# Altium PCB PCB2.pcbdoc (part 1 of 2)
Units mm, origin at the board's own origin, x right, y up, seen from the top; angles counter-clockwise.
Board outline 189.74 x 136.02 mm, 2 copper layers (Top Layer, Bottom Layer); 111 components, 66 nets, 434 pads, 460 vias.
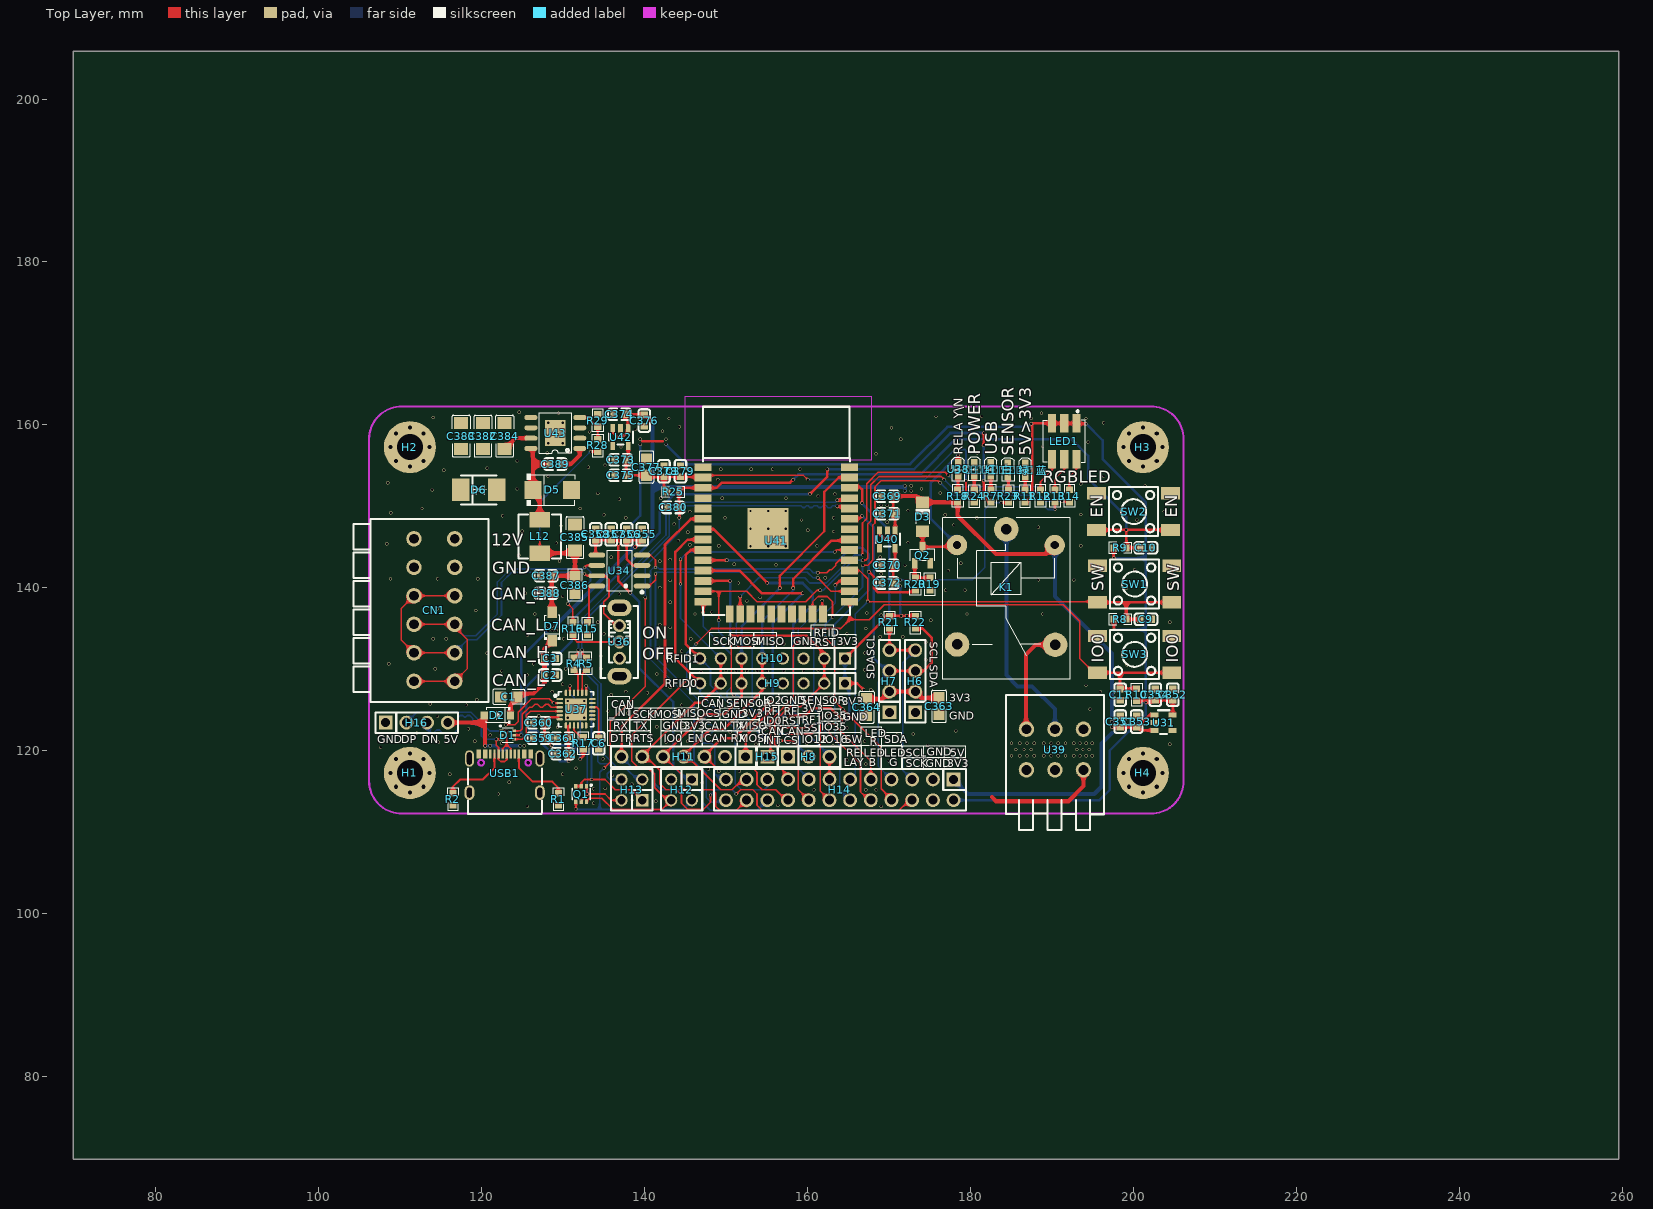
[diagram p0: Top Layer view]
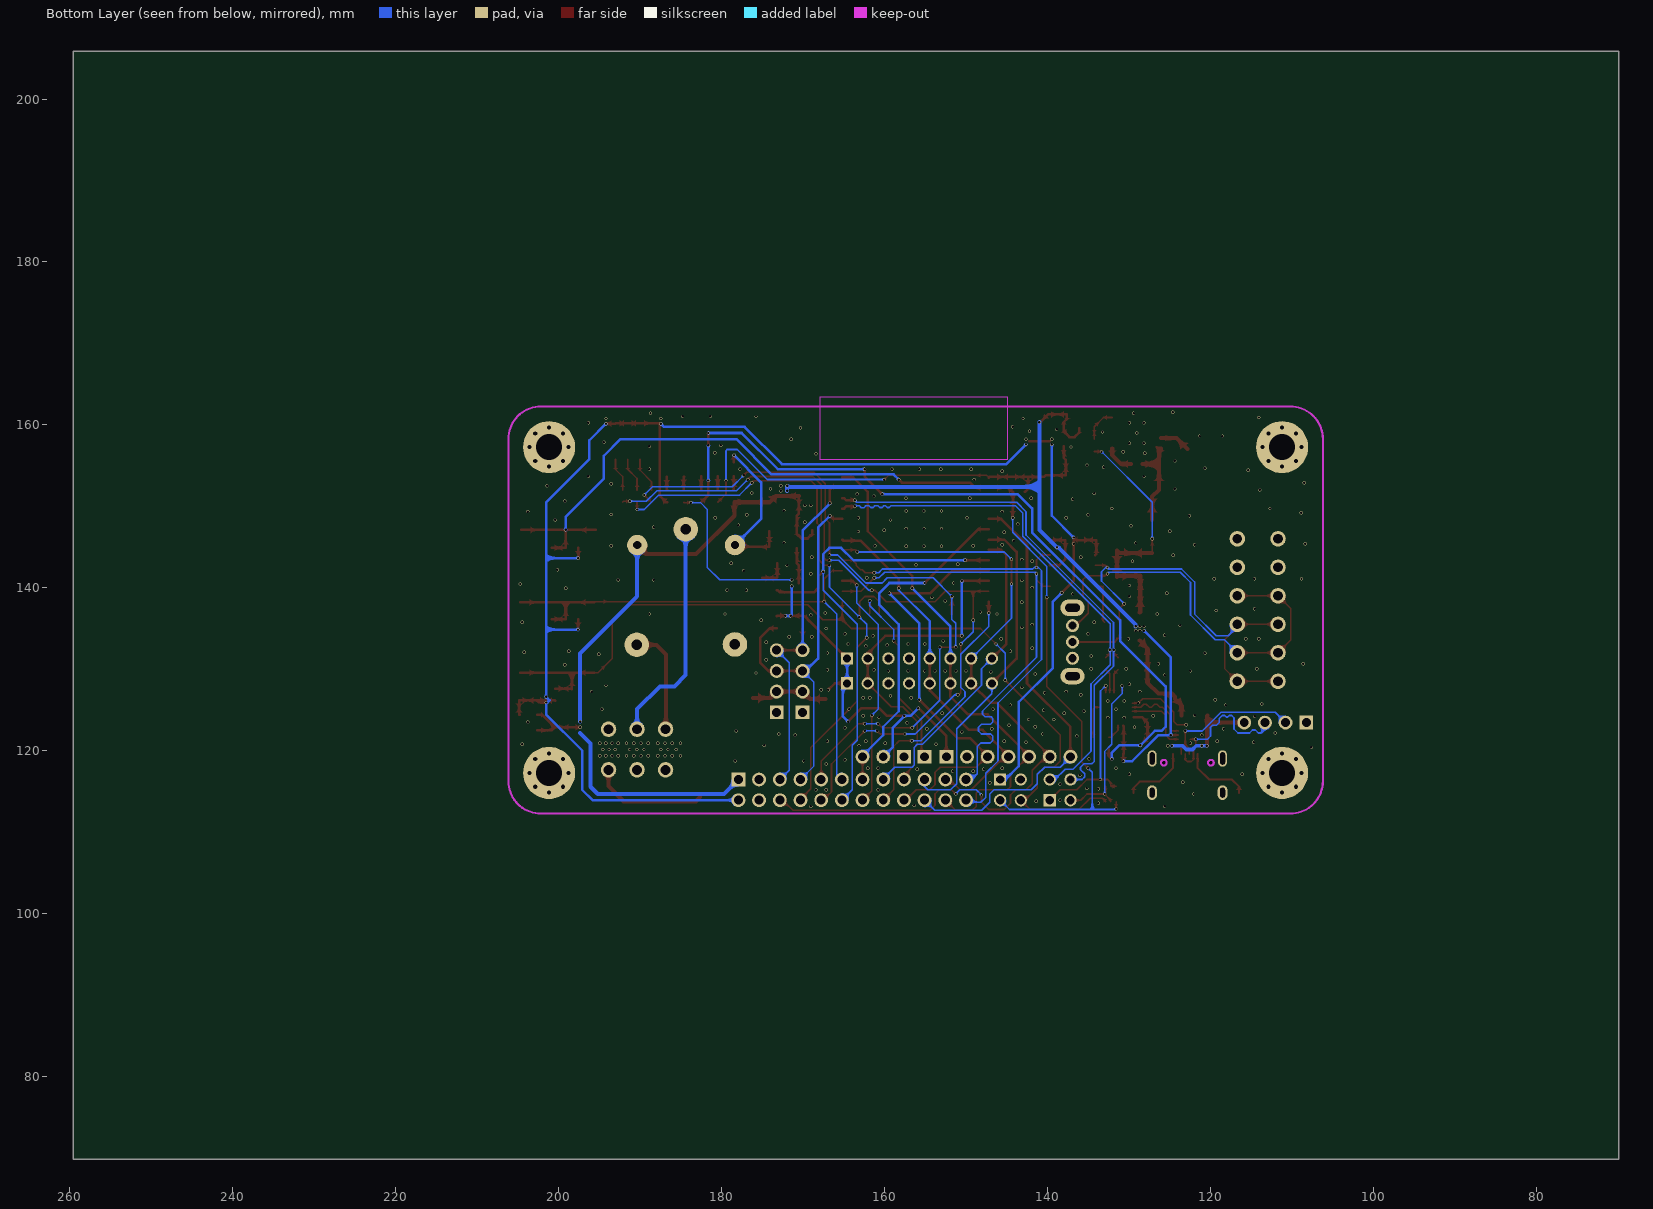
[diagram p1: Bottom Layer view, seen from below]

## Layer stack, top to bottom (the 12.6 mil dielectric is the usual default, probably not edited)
Top Layer: signal copper (thickness not stored)
Dielectric: dielectric 0.32, FR-4, Dk 4.8
Bottom Layer: signal copper (thickness not stored)

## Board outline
259.588,69.85 69.85,69.85 69.85,205.867 259.588,205.867

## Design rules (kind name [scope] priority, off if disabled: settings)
Clearance copperThickness1oz [All] p1: gap=0.178 ignorepadtopadclearanceinfootprint=FALSE except(0.099: Track-Track Track-SMDPad SMDPad-SMDPad Track-THPad SMDPad-THPad THPad-THPad Track-Via SMDPad-Via THPad-Via Via-Via Track-Fill SMDPad-Fill THPad-Fill Via-Fill Fill-Fill Track-Region SMDPad-Region THPad-Region Via-Region Fill-Region Region-Region Track-Poly SMDPad-Poly THPad-Poly Via-Poly Fill-Poly Region-Poly Poly-Poly Track-Text SMDPad-Text THPad-Text Via-Text Fill-Text Region-Text Poly-Text Text-Text Track-Hole SMDPad-Hole THPad-Hole Via-Hole Fill-Hole Region-Hole Poly-Hole Text-Hole; 0.254: SMDPad-Sheet; 0.3: Track-Sheet THPad-Sheet Via-Sheet Fill-Sheet Region-Sheet Poly-Sheet Text-Sheet Sheet-Hole)
Clearance copperThickness2oz [All] p1: gap=0.178 ignorepadtopadclearanceinfootprint=FALSE except(0.152: Track-SMDPad SMDPad-SMDPad Track-THPad SMDPad-THPad THPad-THPad Track-Via SMDPad-Via THPad-Via Via-Via Track-Fill SMDPad-Fill THPad-Fill Via-Fill Fill-Fill SMDPad-Region THPad-Region Via-Region Fill-Region Region-Region Track-Poly SMDPad-Poly THPad-Poly Via-Poly Fill-Poly Poly-Poly Track-Text SMDPad-Text THPad-Text Via-Text Fill-Text Region-Text Poly-Text Text-Text Track-Hole SMDPad-Hole THPad-Hole Via-Hole Fill-Hole Region-Hole Poly-Hole Text-Hole; 0.203: Track-Track; 0.3: Track-Region Region-Poly Track-Sheet SMDPad-Sheet THPad-Sheet Via-Sheet Fill-Sheet Region-Sheet Poly-Sheet Text-Sheet Sheet-Hole)
Clearance copperThicknessInner0.5oz [All] p1: gap=0.178 ignorepadtopadclearanceinfootprint=FALSE except(0.089: Track-Track; 0.152: Track-SMDPad SMDPad-SMDPad Track-THPad SMDPad-THPad THPad-THPad Track-Via SMDPad-Via THPad-Via Via-Via Track-Fill SMDPad-Fill THPad-Fill Via-Fill Fill-Fill SMDPad-Region THPad-Region Via-Region Fill-Region Region-Region Track-Poly SMDPad-Poly THPad-Poly Via-Poly Fill-Poly Poly-Poly Track-Text SMDPad-Text THPad-Text Via-Text Fill-Text Region-Text Poly-Text Text-Text Track-Hole SMDPad-Hole THPad-Hole Via-Hole Fill-Hole Region-Hole Poly-Hole Text-Hole; 0.3: Track-Region Region-Poly Track-Sheet SMDPad-Sheet THPad-Sheet Via-Sheet Fill-Sheet Region-Sheet Poly-Sheet Text-Sheet Sheet-Hole)
DiffPairsRouting differentialPair [All] p1: maxuncoupledlength=10 maxlimit=7.874 mostfreqgap=7.874 toplayer_minwidth=5 toplayer_prefwidth=10 toplayer_maxwidth=100 bottomlayer_minwidth=5 bottomlayer_prefwidth=10 bottomlayer_maxwidth=100
PasteMaskExpansion pasteMaskExpansion [All] p1:
PlaneConnect innerPlane [All] p1: planeconnectstyle=Relief reliefexpansion=0.508 reliefentries=4 reliefconductorwidth=0.254 reliefairgap=0.254
PolygonConnect copperRegionvusb [All] p1: connectstyle=Direct reliefentries=4 reliefconductorwidth=10 polygonreliefangle="90 Angle" airgapwidth=10
PolygonConnect copperRegion0p2 [All] p1: connectstyle=Direct reliefentries=4 reliefconductorwidth=10 polygonreliefangle="90 Angle" airgapwidth=10
PolygonConnect copperRegion1 [All] p1: connectstyle=Direct reliefentries=4 reliefconductorwidth=10 polygonreliefangle="90 Angle" airgapwidth=10
RoutingVias viaSize [All] p1: viastyle="Through Hole" holewidth=11.811 minholewidth=11.811 maxholewidth=248.0314 width=15.748 minwidth=15.748 maxwidth=393.7008
SolderMaskExpansion solderMaskExpansion [All] p1: useseparateexpansions=TRUE expansion=2.0079 expansionbottom=2.0079
Width copperThickness1oz [All] p1: maxlimit=394 minlimit=4 preferedwidth=8
Width copperThickness0.5oz [All] p1: maxlimit=100 minlimit=4 preferedwidth=10
Width copperThickness2oz [All] p1: maxlimit=100 minlimit=8 preferedwidth=10

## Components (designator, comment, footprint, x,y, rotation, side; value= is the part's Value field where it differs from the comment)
C1 "CGA0805X5R226M350MT" C0805 123.317,126.619 r180 top
C2 "CL10A106MA8NRNC" C0603 128.397,129.286 r0 top
C3 "CGA0603X7R104K500JT" C0603 128.397,131.318 r0 top
C6 "CGA0603X5R475K250JT" C0603 134.366,120.904 r90 top
C9 "CGA0603X7R104K500JT" C0603 201.549,136.144 r0 top
C10 "CGA0603X7R104K500JT" C0603 201.549,144.907 r0 top
C11 "CGA0603X7R104K500JT" C0603 198.374,126.873 r270 top
C351 "CL10A106MA8NRNC" C0603 198.374,123.571 r270 top
C352 "CL10A106MA8NRNC" C0603 204.851,126.873 r270 top
C353 "CGA0603X7R104K500JT" C0603 200.406,123.571 r270 top
C354 "CGA0603X7R104K500JT" C0603 202.692,126.873 r270 top
C355 "CL10A106MA8NRNC" C0603 139.7,146.558 r270 top
C356 "CGA0603X7R104K500JT" C0603 137.795,146.558 r270 top
C357 "CL10A106MA8NRNC" C0603 135.89,146.558 r270 top
C358 "CGA0603X7R104K500JT" C0603 133.985,146.558 r270 top
C359 "CGA0603X7R104K500JT" C0603 127,121.539 r0 top
C360 "CGA0603X5R475K250JT" C0603 127,123.444 r0 top
C361 "CL10A106MA8NRNC" C0603 129.921,121.539 r0 top
C362 "CGA0603X7R104K500JT" C0603 129.921,119.634 r0 top
C363 "CGA0805X5R226M350MT" C0805 176.149,125.476 r270 top
C364 "CGA0805X5R226M350MT" C0805 167.259,125.349 r270 top
C369 "CL10A106MA8NRNC" C0603 169.799,151.257 r0 top
C370 "CL10A106MA8NRNC" C0603 169.799,142.748 r0 top
C371 "CGA0603X7R104K500JT" C0603 169.799,149.098 r0 top
C372 "CGA0603X7R104K500JT" C0603 169.799,140.589 r0 top
C373 "CL10A106MA8NRNC" C0603 137.033,155.702 r0 top
C374 "CGA0603X7R104K500JT" C0603 136.906,161.29 r0 top
C375 "CGA0603X7R104K500JT" C0603 137.033,153.797 r0 top
C376 "CL10A106MA8NRNC" C0603 139.954,160.528 r90 top
C377 "CGA0805X5R226M350MT" C0805 140.208,154.813 r90 top
C378 "CL10A106MA8NRNC" C0603 142.367,154.305 r90 top
C379 "CGA0603X7R104K500JT" C0603 144.399,154.305 r90 top
C380 "CGA0603X7R104K500JT" C0603 143.51,149.86 r180 top
C382 "HGC1206R5106K500NSPJ" C1206 120.142,158.623 r270 top
C383 "CGA1206X5R226M350NT" C1206 117.475,158.623 r270 top
C384 "CL31B104KBCNNNC" C1206 122.809,158.623 r270 top
C385 "HGC1206R5476M250NSPJ" C1206 131.445,146.177 r270 top
C386 "CGA0805X5R226M350MT" C0805 131.445,140.335 r90 top
C387 "CL10A106MA8NRNC" C0603 127.889,141.478 r0 top
C388 "CGA0603X7R104K500JT" C0603 127.889,139.319 r0 top
C389 "CGA0603X7R104K500JT" C0603 129.032,155.194 r0 top
CN1 "New_Library_2601-1106" CONN-TH_2601-1106 114.172,137.268 r270 top
D1 "USBLC6-2P6_C2827693" SOT-666-6_L1.6-W1.2-P0.50-LS1.6-BL 123.19,121.92 r270 top
D2 "5819W" SOD-123_L2.7-W1.6-LS3.7-FD 121.92,124.333 r0 top
D3 "LL4148-GS08" SOD-80_L3.5-W1.5-RD 174.117,148.717 r270 top
D5 "SS54SMB" SMB_L4.6-W3.6-LS5.3-RD 128.651,152.019 r0 top
D6 "SMBJ28A" SMB_L4.6-W3.6-LS5.3-L-FD 119.634,152.019 r180 top
D7 "DSK34_C7502709" SOD-123FL_L2.7-W1.8-LS3.8-RD 128.651,135.255 r90 top
H1 "Mechanical_MountingHole_Pad" MountingHole:MountingHole_3.2mm_M3_Pad_Via 111.172,117.268 r0 top
H2 "Mechanical_MountingHole_Pad" MountingHole:MountingHole_3.2mm_M3_Pad_Via 111.172,157.268 r0 top
H3 "Mechanical_MountingHole_Pad" MountingHole:MountingHole_3.2mm_M3_Pad_Via 201.172,157.268 r0 top
H4 "Mechanical_MountingHole_Pad" MountingHole:MountingHole_3.2mm_M3_Pad_Via 201.172,117.268 r0 top
H6 "PZ254V-11-04P" HDR-TH_4P-P2.54-V-M 173.228,128.524 r90 top
H7 "PZ254V-11-04P" HDR-TH_4P-P2.54-V-M 170.053,128.524 r90 top
H8 "PZ254V-11-03P" HDR-TH_3P-P2.54-V-M 160.147,119.253 r0 top
H9 "PZ254V-11-08P" HDR-TH_8P-P2.54-V-M 155.702,128.27 r180 top
H10 "PZ254V-11-08P" HDR-TH_8P-P2.54-V-M 155.702,131.318 r180 top
H11 "HX PZ2.54-1x7P ZZ" HDR-TH_7P-P2.54-V-M 144.78,119.253 r180 top
H12 "HX PZ2.54-2x2P ZZ" HDR-TH_HX-PZ2.54-2X2P-ZZ 144.526,115.189 r180 top
H13 "HX PZ2.54-2x2P ZZ" HDR-TH_HX-PZ2.54-2X2P-ZZ 138.43,115.189 r90 top
H14 "PZ254V-12-24P" HDR-TH_24P-P2.54-V-M-R2-C12-S2.54 163.957,115.189 r180 top
H15 "PZ254V-11-01P" HDR-TH_1P-P2.54-V-M 155.067,119.253 r0 top
H16 "PZ254V-11-04P" HDR-TH_4P-P2.54-V-M 112.014,123.444 r0 top
K1 "Relay_SANYOU_SRD_Form_C" Relay_THT:Relay_SPDT_SANYOU_SRD_Series_Form_C 184.404,147.193 r270 top
L12 "FXL0530-100-M" IND-SMD_L5.4-W5.2_FXL0530 127.127,146.304 r270 top
LED1 "TC5050RGBF08-3CJH-AF53A" LED-SMD_6P-L5.0-W5.0-TL_TC5050RGBF08 191.516,157.988 r270 top
LED白 "NCD0603W1" LED0603-RD 182.499,154.432 r270 top
LED红 "SZYY0603R" LED0603-R-RD 180.467,154.559 r270 top
LED绿 "XL-1608PGC-06" LED0603-RD_GREEN 184.658,154.432 r270 top
LED蓝 "SZYY0603B" LED0603-R-RD_BLUE 186.69,154.432 r270 top
Q1 "UMH3N" SC-70-6_L2.2-W1.3-P0.65-LS2.1-BR 132.207,114.681 r90 top
Q2 "BC817_C916383" SOT-23-3_L2.9-W1.3-P1.90-LS2.4-BR 174.117,144.018 r270 top
R1 "0603WAF5101T5E" R0603 129.413,114.046 r270 top
R2 "0603WAF5101T5E" R0603 116.459,114.046 r270 top
R4 "0603WAF220JT5E" R0603 131.318,130.683 r90 top
R5 "0603WAF220JT5E" R0603 132.842,130.683 r90 top
R7 "0603WAF1002T5E" R0603 182.499,151.257 r90 top
R8 "0603WAF1002T5E" R0603 198.374,136.144 r180 top
R9 "0603WAF1002T5E" R0603 198.374,144.907 r180 top
R10 "0603WAF1002T5E" R0603 200.406,126.873 r270 top
R11 "0603WAF1002T5E" R0603 186.69,151.257 r270 top
R12 "0603WAF1001T5E" R0603 188.595,151.257 r90 top
R13 "0603WAF1001T5E" R0603 190.373,151.257 r90 top
R14 "0603WAF1001T5E" R0603 192.151,151.257 r90 top
R15 "0603WAF0000T5E" R0603 132.969,135.001 r270 top
R16 "0603WAF220JT5E" R0603 131.191,135.001 r90 top
R17 "0603WAF4701T5E" R0603 132.461,120.904 r90 top
R18 "0603WAF1002T5E" R0603 178.435,151.257 r90 top
R19 "0603WAF1002T5E" R0603 175.006,140.462 r270 top
R20 "0603WAF1001T5E" R0603 173.228,140.462 r90 top
R21 "0603WAF4701T5E" R0603 170.053,135.763 r270 top
R22 "0603WAF4701T5E" R0603 173.228,135.763 r270 top
R23 "0603WAF1002T5E" R0603 184.658,151.257 r270 top
R24 "0603WAF1002T5E" R0603 180.467,151.257 r270 top
R25 "0603WAF1002T5E" R0603 143.51,151.765 r0 top
R28 "0603WAF1002T5E" R0603 134.239,157.48 r270 top
R29 "FRC0603F3161TS" R0603 134.239,160.528 r90 top
SW1 "KH-6X6X5H-STM" SW-SMD_4P-L6.0-W6.0-P4.50-LS9.0_H5.0 200.152,140.462 r0 top
SW2 "KH-6X6X5H-STM" SW-SMD_4P-L6.0-W6.0-P4.50-LS9.0_H5.0 200.025,149.352 r0 top
SW3 "KH-6X6X5H-STM" SW-SMD_4P-L6.0-W6.0-P4.50-LS9.0_H5.0 200.152,131.826 r0 top
U31 "ME6211C30M5G-N" SOT-23-5_L2.9-W1.6-P0.95-LS2.8-BL 203.708,123.444 r270 top
U34 "TJA1051T/3/1J" SOIC-8_L4.9-W3.9-P1.27-LS6.0-BL 136.906,142.113 r90 top
U36 "HX SS12D07VG5" SW-TH_SS12D07VG3 136.906,133.35 r270 top
U37 "CP2104-F03-GMR" QFN-24_L4.0-W4.0-P0.50-BL-EP2.7 131.572,125.095 r270 top
U38 "MHT192WDT-GOLD" LED0603-RD-YELLOW 178.435,154.432 r270 top
U39 "2601-1103" CONN-TH_6P-P3.50_2601-1103 190.373,120.142 r0 top
U40 "ME6211C30M5G-N" SOT-23-5_L2.9-W1.6-P0.95-LS2.8-BL 169.799,145.953 r180 top
U41 "ESP32-WROOM-32D-N4" WIFIM-SMD_39P-L25.5-W18.0-P1.27-BL 156.172,145.796 r270 top
U42 "ME6211C30M5G-N" SOT-23-5_L2.9-W1.6-P0.95-LS2.8-BL 137.033,158.496 r180 top
U43 "TPS5450MDDAREP" POWERPAD-SO-8_L4.9-W3.9-P1.27-LS6.0-BL-EP 129.032,159.004 r90 top
USB1 "TYPE-C 16PIN 2MD(073)" USB-C-SMD_TYPE-C-6PIN-2MD-073 122.809,117.221 r0 top

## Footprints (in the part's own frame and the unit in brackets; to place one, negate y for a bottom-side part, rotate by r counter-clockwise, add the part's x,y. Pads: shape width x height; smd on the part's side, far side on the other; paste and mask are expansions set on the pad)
C0603 [mm]
  rect 0.8x0.9 smd: 1(-0.7,0) 2(0.7,0)
  silkscreen extent -1.39,-0.71 1.39,0.71
C0805 [mm]
  rect 1.41x1.35 smd: 1(-1,0) 2(1,0)
  silkscreen extent -1.96,-0.9 1.96,0.9
C1206 [mm]
  rect 1.485x1.728 smd: 1(-1.593,0) 2(1.593,0)
  silkscreen extent -2.56,-1.09 2.56,1.09
CONN-TH_6P-P3.50_2601-1103 [mm]
  round 1.9 hole 1.2: 1(-3.5,2.5) 2(-3.5,-2.5) 3(0,2.5) 4(0,-2.5) 5(3.5,2.5) 6(3.5,-2.5)
  silkscreen extent -6,-9.9 6,6.7
CONN-TH_2601-1106 [mm]
  round 1.9 hole 1.2: 1(-8.75,-2.5) 1(-8.75,2.5) 2(-5.25,2.5) 2(-5.25,-2.5) 3(-1.75,2.5) 3(-1.75,-2.5) 4(1.75,2.5) 4(1.75,-2.5) 5(5.25,2.5) 5(5.25,-2.5) 6(8.75,-2.5) 6(8.75,2.5)
  silkscreen extent -11.19,-9.93 11.31,6.65
HDR-TH_1P-P2.54-V-M [mm]
  rect 1.7x1.7 hole 1.1: 1(0,0)
  silkscreen extent -1.27,-1.27 1.27,1.27
HDR-TH_3P-P2.54-V-M [mm]
  rect 1.7x1.7 hole 1.1: 1(-2.54,0)
  round 1.7 hole 1.1: 2(0,0) 3(2.54,0)
  silkscreen extent -3.81,-1.25 3.81,1.25
HDR-TH_4P-P2.54-V-M [mm]
  rect 1.7x1.7 hole 1.1: 1(-3.81,0)
  round 1.7 hole 1.1: 2(-1.27,0) 3(1.27,0) 4(3.81,0)
  silkscreen extent -5.08,-1.27 5.08,1.27
HDR-TH_7P-P2.54-V-M [mm]
  rect 1.7x1.7 hole 1.1: 1(-7.62,0)
  round 1.7 hole 1.1: 2(-5.08,0) 3(-2.54,0) 4(0,0) 5(2.54,0) 6(5.08,0) 7(7.62,0)
  silkscreen extent -8.89,-1.25 8.89,1.25
HDR-TH_8P-P2.54-V-M [mm]
  rect 1.5x1.5 hole 1: 1(-8.89,0)
  round 1.5 hole 1: 2(-6.35,0) 3(-3.81,0) 4(-1.27,0) 5(1.27,0) 6(3.81,0) 7(6.35,0) 8(8.89,0)
  silkscreen extent -10.16,-1.27 10.16,1.27
HDR-TH_24P-P2.54-V-M-R2-C12-S2.54 [mm]
  rect 1.7x1.7 hole 1.1: 1(-13.97,-1.27)
  round 1.7 hole 1.1: 2(-13.97,1.27) 3(-11.43,-1.27) 4(-11.43,1.27) 5(-8.89,-1.27) 6(-8.89,1.27) 7(-6.35,-1.27) 8(-6.35,1.27) 9(-3.81,-1.27) 10(-3.81,1.27) 11(-1.27,-1.27) 12(-1.27,1.27) 13(1.27,-1.27) 14(1.27,1.27) 15(3.81,-1.27) 16(3.81,1.27) 17(6.35,-1.27) 18(6.35,1.27) 19(8.89,-1.27) 20(8.89,1.27) 21(11.43,-1.27) 22(11.43,1.27) 23(13.97,-1.27) 24(13.97,1.27)
  silkscreen extent -15.47,-2.54 15.47,2.54
HDR-TH_HX-PZ2.54-2X2P-ZZ [mm]
  rect 1.5x1.5 hole 1.02: 1(-1.27,-1.27)
  round 1.5 hole 1.02: 2(-1.27,1.27) 3(1.27,-1.27) 4(1.27,1.27)
  silkscreen extent -2.54,-2.54 2.54,2.54
IND-SMD_L5.4-W5.2_FXL0530 [mm]
  rect 1.9x2.5 smd: 1(-2.05,0) 2(2.05,0)
  silkscreen extent -2.7,-2.6 2.7,2.6
LED0603-R-RD [mm]
  rect 0.8x0.8 smd: 1(0.851,0) 2(-0.851,0)
  silkscreen extent -1.44,-0.75 1.44,0.75
LED0603-R-RD_BLUE [mm]
  rect 0.8x0.8 smd: 1(0.8,0.038) 2(-0.902,0.038)
  silkscreen extent -1.49,-0.71 1.39,0.79
LED0603-RD [mm]
  rect 0.8x0.8 smd: 1(-0.963,-0.005) 2(0.739,-0.005)
  silkscreen extent -1.55,-0.76 1.33,0.75
LED0603-RD-YELLOW [mm]
  rect 0.8x0.8 smd: 1(-0.965,0.038) 2(0.737,0.038)
  silkscreen extent -1.55,-0.71 1.33,0.79
LED0603-RD_GREEN [mm]
  rect 0.8x0.8 smd: 1(-0.911,-0.05) 2(0.791,-0.05)
  silkscreen extent -1.5,-0.8 1.38,0.7
LED-SMD_6P-L5.0-W5.0-TL_TC5050RGBF08 [mm]
  rect 2.265x1 smd: 1(-2.208,1.5) 2(-2.208,0) 3(-2.208,-1.5) 4(2.208,-1.5) 5(2.208,0) 6(2.208,1.5)
  silkscreen extent -3.81,-2.58 2.58,2.58
MountingHole:MountingHole_3.2mm_M3_Pad_Via [mm]
  round 0.8 hole 0.5: 1(-2.4,0) 1(-1.697,-1.697) 1(-1.697,1.697) 1(0,-2.4) 1(0,2.4) 1(1.697,-1.697) 1(1.697,1.697) 1(2.4,0)
  round 6.4 hole 3.2: 1(0,0)
POWERPAD-SO-8_L4.9-W3.9-P1.27-LS6.0-BL-EP [mm]
  oval 0.6x1.6 smd: 1(-1.905,-3) 2(-0.635,-3) 3(0.635,-3) 4(1.905,-3) 5(1.905,3) 6(0.635,3) 7(-0.635,3) 8(-1.905,3)
  rect 3.2x2.5 smd: 9(0,0)
  silkscreen extent -2.5,-2 2.5,2
QFN-24_L4.0-W4.0-P0.50-BL-EP2.7 [mm]
  oval 0.28x0.8 smd: 1(-1.25,-2) 2(-0.75,-2) 3(-0.25,-2) 4(0.25,-2) 5(0.75,-2) 6(1.25,-2) 13(1.25,2) 14(0.75,2) 15(0.25,2) 16(-0.25,2) 17(-0.75,2) 18(-1.242,2)
  oval 0.8x0.28 smd: 7(2,-1.25) 8(2,-0.75) 9(2,-0.25) 10(2,0.25) 11(2,0.75) 12(2,1.25) 19(-2,1.25) 20(-2,0.75) 21(-2,0.25) 22(-2,-0.25) 23(-2,-0.75) 24(-2,-1.25)
  rect 2.7x2.7 smd: 25(0.012,0)
  silkscreen extent -2.14,-2.79 2.16,2.15
R0603 [mm]
  rect 0.806x0.864 smd: 1(-0.753,0) 2(0.753,0)
  silkscreen extent -1.39,-0.66 1.39,0.66
Relay_THT:Relay_SPDT_SANYOU_SRD_Series_Form_C [mm]
  round 3 hole 1.3: 1(0,0) 3(14.15,-6.05) 4(14.2,6)
  round 2.5 hole 1: 2(1.95,-6.05) 5(1.95,5.95)
  silkscreen extent -1.4,-7.8 18.4,7.8
SC-70-6_L2.2-W1.3-P0.65-LS2.1-BR [mm]
  rect 0.6x0.42 smd: 1(0.95,-0.65) 2(0.95,0) 3(0.95,0.65) 4(-0.95,0.65) 5(-0.95,0) 6(-0.95,-0.65)
  silkscreen extent -0.7,-1.34 1.22,1.1
SMB_L4.6-W3.6-LS5.3-L-FD [mil]
  rect 85x108 smd: 1(-87,0) 2(87,0)
  silkscreen extent -85,-70 85,70
SMB_L4.6-W3.6-LS5.3-RD [mm]
  rect 2.047x2.192 smd: 1(-2.361,0) 2(2.361,0)
  silkscreen extent -3.12,-1.96 2.74,1.96
SOD-80_L3.5-W1.5-RD [mm]
  rect 1.44x1.62 smd: 1(-1.765,0) 2(1.765,0)
  silkscreen extent -0.84,-0.83 0.84,0.83
SOD-123_L2.7-W1.6-LS3.7-FD [mm]
  rect 0.88x0.96 smd: 1(-1.61,0) 2(1.61,0)
  silkscreen extent -1.38,-1 1.6,1
SOD-123FL_L2.7-W1.8-LS3.8-RD [mm]
  rect 1.4x1.2 smd: 1(-1.735,0) 2(1.735,0)
  silkscreen extent -1.6,-1 1.38,1
SOIC-8_L4.9-W3.9-P1.27-LS6.0-BL [mm]
  oval 0.588x2.045 smd: 1(-1.905,-2.772) 2(-0.635,-2.772) 3(0.635,-2.772) 4(1.905,-2.772) 5(1.905,2.772) 6(0.635,2.772) 7(-0.635,2.772) 8(-1.905,2.772)
  silkscreen extent -2.8,-2.92 2.53,1.52
SOT-23-3_L2.9-W1.3-P1.90-LS2.4-BR [mm]
  rect 1.25x0.7 smd: 1(1,-0.95) 2(1,0.95) 3(-1,0)
  silkscreen extent -0.73,-1.53 0.73,1.53
SOT-23-5_L2.9-W1.6-P0.95-LS2.8-BL [mm]
  rect 0.6x1 smd: 1(-0.95,-1.1) 2(0,-1.1) 3(0.95,-1.1) 4(0.95,1.1) 5(-0.95,1.1)
  silkscreen extent -1.52,-0.7 1.4,0.89
SOT-666-6_L1.6-W1.2-P0.50-LS1.6-BL [mm]
  rect 0.3x0.5 smd: 1(-0.5,-0.75) 2(0,-0.75) 3(0.5,-0.75) 4(0.5,0.75) 5(0,0.75) 6(-0.5,0.75)
  silkscreen extent -1.21,-1.01 0.88,0.68
SW-SMD_4P-L6.0-W6.0-P4.50-LS9.0_H5.0 [mm]
  rect 2.3x1.5 smd: 1(-4.55,2.25) 2(4.55,2.25) 3(-4.55,-2.25) 4(4.55,-2.25)
  silkscreen extent -3,-3 3,3
SW-TH_SS12D07VG3 [mm]
  round 1.6 hole 1: 1(-2,0) 2(0,0) 3(2,0)
  oval 2x3 hole 1 slot 1.8 at 90 deg: 4(4.2,0) 5(-4.2,0)
  silkscreen extent -4.4,-2.3 4.4,2.3
USB-C-SMD_TYPE-C-6PIN-2MD-073 [mm]
  rect 0.55x1.1 smd: 1(-3.2,2.375) 2(-2.4,2.375) 11(2.4,2.375) 12(3.2,2.375)
  rect 0.3x1.1 smd: 3(-1.75,2.375) 4(-1.25,2.375) 5(-0.75,2.375) 6(-0.25,2.375) 7(0.25,2.375) 8(0.75,2.375) 9(1.25,2.375) 10(1.75,2.375)
  oval 1.1x2 hole 0.6 slot 1.5 at 90 deg: 13(-4.325,1.825) 14(4.325,1.825)
  oval 1.2x1.8 hole 0.6 slot 1.2 at 90 deg: 13(-4.325,-2.375) 14(4.325,-2.375)
  Multi-Layer board cut-out: -2.54,1.305 -2.589,1.477 -2.717,1.603 -2.89,1.648 -3.063,1.603 -3.191,1.477 -3.24,1.305 -3.24,1.305 -3.191,1.133 -3.063,1.007 -2.89,0.962 -2.717,1.007 -2.589,1.133 -2.54,1.305
  Multi-Layer board cut-out: 3.24,1.305 3.206,1.457 3.108,1.579 2.968,1.646 2.812,1.646 2.672,1.579 2.575,1.457 2.54,1.305 2.54,1.305 2.575,1.153 2.672,1.031 2.812,0.964 2.968,0.964 3.108,1.031 3.205,1.153 3.24,1.305
  Multi-Layer keep-out circle w0.254: c-2.89,1.305 r0.35
  Multi-Layer keep-out circle w0.254: c2.89,1.305 r0.35
  silkscreen extent -4.5,-4.97 4.57,0.6
WIFIM-SMD_39P-L25.5-W18.0-P1.27-BL [mm]
  rect 0.95x2.1 smd: 1(-9.015,-9) 2(-7.745,-9) 3(-6.475,-9) 4(-5.205,-9) 5(-3.935,-9) 6(-2.665,-9) 7(-1.395,-9) 8(-0.125,-9) 9(1.145,-9) 10(2.415,-9) 11(3.685,-9) 12(4.955,-9) 13(6.225,-9) 14(7.495,-9) 25(7.495,9) 26(6.225,9) 27(4.955,9) 28(3.685,9) 29(2.415,9) 30(1.145,9) 31(-0.125,9) 32(-1.395,9) 33(-2.665,9) 34(-3.935,9) 35(-5.205,9) 36(-6.475,9) 37(-7.745,9) 38(-9.015,9)
  rect 2.1x0.95 smd: 15(9.015,-5.715) 16(9.015,-4.445) 17(9.015,-3.175) 18(9.015,-1.905) 19(9.015,-0.635) 20(9.015,0.635) 21(9.015,1.905) 22(9.015,3.175) 23(9.015,4.445) 24(9.015,5.715)
  rect 5x5 smd: 39(-1.472,-1.017)
  silkscreen extent -16.44,-9.02 9.12,9.02

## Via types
v1: diameter 0.4, hole 0.3, Top Layer to Bottom Layer, 460 vias

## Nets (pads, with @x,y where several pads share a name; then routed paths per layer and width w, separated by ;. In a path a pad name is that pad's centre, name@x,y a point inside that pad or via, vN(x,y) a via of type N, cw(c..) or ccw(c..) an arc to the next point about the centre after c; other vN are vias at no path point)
3.3_SENSOR: C363.1 C364.1 C370.2 C372.2 H6.2 H7.2 H8.2 H9.1 H10.1 H11.1 R21.1 R22.1 R23.2 U40.5 | length 84.9
  Top Layer w0.2: v1(183.769,150.462) 184.616,150.462 R23.2@184.658,150.504
  Top Layer w0.312: H11.1@152.4,119.253 152.4,121.793 v1(155.829,125.222) ; v1(157.543,124.269) 159.702,124.269 160.655,125.222 162.814,125.222 v1(164.465,123.571) ; H9.1@164.592,128.27 166.1,128.27 v1(166.878,127.492) ; H10.1@164.592,131.318 169.79,136.516 R21.1@170.053,136.516 170.095,136.558 v1(171.519,136.558) v1(172.154,136.558) 173.186,136.558 R22.1@173.228,136.516 ; C372.2@170.499,140.589 C370.2@170.499,142.748 170.749,142.998 U40.5@170.749,144.853
  Top Layer w0.5: C364.1@167.259,126.349 169.148,126.349 H7.2@170.053,127.254 H6.2@173.228,127.254 174.006,126.476 C363.1@176.149,126.476
  Bottom Layer w0.2: v1(171.384,140.97) 180.213,140.97 181.737,142.494 181.737,149.606 182.593,150.462 v1(183.769,150.462)
  Bottom Layer w0.312: v1(155.829,125.222) 156.781,124.269 v1(157.543,124.269) 159.004,122.809 159.004,120.396 H8.2@160.147,119.253 ; v1(164.465,123.571) 165.1,124.206 165.1,127.762 H9.1@164.592,128.27 H10.1@164.592,131.318 ; v1(171.384,140.208) 171.384,136.718 171.544,136.558 v1(172.154,136.558)
  other v1: 167.767,127.492
3V3: C352.2 C354.2 C357.2 C358.2 H12.1 H14.2 LED1.1 LED1.2 LED1.3 R8.2 R9.2 R10.2 R11.2 U31.5 U34.5 | length 206.3
  Top Layer w0.312: U34.5@134.134,144.018 133.985,144.167 C358.2@133.985,145.858 C357.2@135.89,145.858 136.46,145.858 v1(136.779,146.177) v1(136.779,145.415) 136.779,140.843 v1(138.239,139.382) ; 139.7,157.988 142.24,157.988 ; R11.2@186.69,150.504 186.826,150.504 187.579,151.257 187.579,160.196 LED1.3@190.016,160.196 LED1.2@191.516,160.196 LED1.1@193.016,160.196 193.065,160.147 v1(194.183,160.147) ; v1(197.579,143.637) 197.579,144.865 R9.2@197.621,144.907 ; v1(197.621,134.874) R8.2@197.621,136.144 ; R10.2@200.406,126.12 200.459,126.173 C354.2@202.692,126.173 ; v1(201.549,125.919) 202.438,125.919 C354.2@202.692,126.173 ; U31.5@204.808,124.394 204.851,124.437 C352.2@204.851,126.173 C354.2@202.692,126.173
  Bottom Layer w0.312: v1(136.779,146.177) 139.446,148.844 v1(139.446,157.607) ; v1(138.239,139.382) 139.319,138.303 139.319,130.175 143.51,125.984 143.51,118.11 145.161,116.459 H12.1@145.796,116.459 ; v1(142.621,157.607) 145.034,155.194 172.593,155.194 177.165,159.766 187.071,159.766 v1(187.452,160.147) ; H14.2@177.927,113.919 195.834,113.919 197.104,115.189 197.104,120.015 201.549,124.46 201.549,125.749 201.125,126.173 v1(201.549,126.597) 201.549,134.92 ; v1(194.183,160.147) 196.215,158.115 196.215,155.829 201.549,150.495 201.549,143.637 ; v1(197.579,143.637) 201.549,143.637 ; v1(197.621,134.874) 201.503,134.874 201.549,134.92 ; 201.549,134.92 201.549,143.637
  other v1: 139.446,158.242 142.621,158.242 187.452,160.782 194.183,160.787
3V3_POWER: C373.2 C375.2 C377.1 C378.1 C379.1 R24.2 R25.1 U41.2 U42.5 | length 56.2
  Top Layer w0.2: U41.2@147.172,153.541 147.428,153.797 159.512,153.797 v1(160.02,153.289) ; v1(179.451,153.162) 179.451,151.52 R24.2@180.467,150.504
  Top Layer w0.312: U42.5@137.983,157.396 137.983,155.952 C373.2@137.733,155.702 C375.2@137.733,153.797 140.192,153.797 C377.1@140.208,153.813 140.416,153.605 C378.1@142.367,153.605 ; R25.1@142.757,151.765 142.367,152.155 C378.1@142.367,153.605 ; U41.2@147.172,153.541 147.108,153.605 C379.1@144.399,153.605 C378.1@142.367,153.605
  Bottom Layer w0.2: v1(160.02,153.289) 174.371,153.289 178.054,156.972 179.324,156.972 179.451,156.845 v1(179.451,153.162)
$1N379: R1.1 USB1.10 | length 8.2
  Top Layer w0.254: USB1.10@124.559,119.596 124.559,117.884 126.238,116.205 128.651,116.205 129.413,115.443 R1.1@129.413,114.799
$1N383: R2.1 USB1.4 | length 8.5
  Top Layer w0.254: R2.1@116.459,114.799 116.459,115.57 117.348,116.459 120.142,116.459 121.539,117.856 121.539,119.576 USB1.4@121.559,119.596
$1N1005: D1.4 U37.4 | length 8.5
  Top Layer w0.2: D1.4@123.94,121.42 124.976,121.42 125.476,121.92 125.476,124.333 125.988,124.845 U37.4@129.572,124.845
$1N1016: D1.6 U37.3 | length 8.5
  Top Layer w0.2: D1.6@123.94,122.42 123.948,122.428 124.714,122.428 124.968,122.682 124.968,124.46 125.853,125.345 126.177,125.345 126.524,125.692 126.847,125.692 127.184,125.354 127.494,125.354 127.847,125.708 128.163,125.708 128.526,125.345 U37.3@129.572,125.345
$1N2492: LED白.2 R7.2 | length 1.7
  Top Layer w0.312: LED白.2@182.494,153.693 182.499,153.688 R7.2@182.499,152.01
$1N3538: LED蓝.1 R11.1 | length 1.6
  Top Layer w0.312: R11.1@186.69,152.01 186.728,152.048 LED蓝.1@186.728,153.632
$1N5096: LED1.4 R12.2 | length 4.4
  Top Layer w0.2: R12.2@188.595,152.01 188.595,153.035 190.016,154.456 LED1.4@190.016,155.78
$1N5100: LED1.5 R13.2 | length 4.2
  Top Layer w0.2: R13.2@190.373,152.01 190.373,153.416 191.516,154.559 LED1.5@191.516,155.78
$1N5105: LED1.6 R14.2 | length 4.1
  Top Layer w0.2: R14.2@192.151,152.01 192.151,153.67 193.016,154.535 LED1.6@193.016,155.78
$1N6214: R15.1 U34.8 | length 5.4
  Top Layer w0.2: R15.1@132.969,135.754 133.169,135.954 133.169,140.027 133.35,140.208 U34.8@134.134,140.208
$1N6447: R16.1 U36.2 | length 6.3
  Top Layer w0.2: R16.1@131.191,134.248 131.191,133.858 131.699,133.35 U36.2@136.906,133.35
$1N8585: C6.2 U37.16 | length 4.4
  Top Layer w0.2: U37.16@133.572,125.345 133.576,125.349 134.112,125.349 134.366,125.095 C6.2@134.366,121.604
$1N8799: R4.1 U37.21 | length 3
  Top Layer w0.2: R4.1@131.318,129.93 131.822,129.426 U37.21@131.822,127.095
$1N8801: R5.1 U37.20 | length 3.1
  Top Layer w0.2: U37.20@132.322,127.095 132.322,129.41 R5.1@132.842,129.93
$1N8937: R17.2 U37.9 | length 2.1
  Top Layer w0.2: U37.9@131.322,123.095 131.322,122.513 132.178,121.657 R17.2@132.461,121.657
$1N9236: R18.2 U38.2 | length 1.7
  Top Layer w0.312: U38.2@178.473,153.695 178.473,152.099 R18.2@178.562,152.01
$1N9240: D3.2 K1.2 Q2.3 U38.1 | length 20.9
  Top Layer w0.312: D3.2@174.117,146.952 Q2.3@174.117,145.018 178.129,145.018 K1.2@178.354,145.243 ; U38.1@178.473,155.397 v1(178.473,156.286)
  Bottom Layer w0.312: K1.2@178.354,145.243 175.133,148.464 175.133,152.946 v1(178.473,156.286)
$1N9454: Q2.1 R19.1 R20.2 | length 3.6
  Top Layer w0.312: Q2.1@173.167,143.018 173.167,141.276 R20.2@173.228,141.215 R19.1@175.006,141.215
$1N9531: K1.4 U39.1 U39.2 | length 13.3
  Top Layer w0.5: U39.1@186.873,122.642 186.817,122.698 186.817,131.826 187.984,132.993 K1.4@190.404,132.993
  other v1: 185.039,119.38 186.055,119.38 186.944,119.38 187.833,119.38 185.547,120.142 186.563,120.142 187.452,120.142 185.039,120.904 186.055,120.904 186.944,120.904 187.833,120.904
$1N9535: K1.1 U39.3 U39.4 | length 28.1
  Bottom Layer w0.5: K1.1@184.404,147.193 184.404,129.286 185.801,127.889 187.579,127.889 190.373,125.095 U39.3@190.373,122.642
  other v1: 189.005,119.38 189.894,119.38 190.783,119.38 191.672,119.38 189.513,120.142 190.402,120.142 191.291,120.142 189.005,120.904 189.894,120.904 190.783,120.904 191.672,120.904
$1N9540: K1.3 U39.5 U39.6 | length 14.2
  Top Layer w0.5: 182.626,114.3 183.134,113.792 192.024,113.792 193.873,115.641 U39.6@193.873,117.642
  other v1: 192.681,119.38 193.443,119.38 194.205,119.38 194.967,119.38 193.062,120.142 193.824,120.142 194.586,120.142 192.681,120.904 193.443,120.904 194.205,120.904 194.967,120.904
$1N10830: LED绿.2 R23.1 | length 1.7
  Top Layer w0.312: LED绿.2@184.608,153.641 184.658,153.591 R23.1@184.658,152.01
$1N11549: LED红.1 R24.1 | length 1.7
  Top Layer w0.312: R24.1@180.467,152.01 LED红.1@180.467,153.708
$1N13650: C389.1 D5.1 L12.1 U43.8 | length 11.4
  Top Layer w0.5: U43.8@126.032,157.099 126.238,157.099 126.29,157.047 126.29,155.145 ; L12.1@127.127,148.354 127.127,151.182 D5.1@126.29,152.019 126.29,155.145 ; C389.1@128.332,155.194 126.339,155.194 126.29,155.145
$1N13751: C385.2 C386.2 C387.2 C388.2 D7.2 L12.2 R28.2 | length 31.1
  Top Layer w0.2: L12.2@127.127,144.254 v1(127.127,146.03) ; v1(133.35,156.727) R28.2@134.239,156.727
  Top Layer w0.5: L12.2@127.127,144.254 131.115,144.254 C385.2@131.445,144.584 C386.2@131.445,141.335 131.302,141.478 C387.2@128.589,141.478 C388.2@128.589,139.319 128.589,137.052 D7.2@128.651,136.99
  Bottom Layer w0.2: v1(127.127,146.03) 127.127,150.504 v1(133.35,156.727)
$1N13789: C389.2 U43.1 | length 3.6
  Top Layer w0.5: C389.2@129.732,155.194 130.937,155.194 132.032,156.289 U43.1@132.032,157.099
+5V: C1.1 C2.1 C3.1 C351.2 C353.2 C355.2 C356.2 C361.2 C362.2 C369.2 C371.2 C374.2 C376.2 D1.5 D2.2 D3.1 D7.1 H14.1 K1.5 R18.1 U31.1 U31.3 U34.3 U37.7 U37.8 U40.1 U40.3 U42.1 U42.3 | length 208.1
  Top Layer w0.254: D1.5@123.94,121.92 v1(124.829,121.92)
  Top Layer w0.312: v1(130.657,118.712) 130.657,119.598 C362.2@130.621,119.634 C361.2@130.621,121.539 130.621,123.001 U37.8@130.683,123.063 ; U42.3@136.083,159.596 136.083,159.065 136.652,158.496 137.287,158.496 137.983,159.192 U42.1@137.983,159.596 137.983,160.34 137.606,160.717 C374.2@137.606,161.29 139.892,161.29 C376.2@139.954,161.228 140.843,160.339 v1(140.97,160.339) ; v1(138.811,144.951) 138.811,144.969 C355.2@139.7,145.858 C356.2@137.795,145.858 137.795,143.51 138.557,142.748 U34.3@139.678,142.748 ; U40.3@168.849,147.053 168.849,146.619 169.418,146.05 170.18,146.05 170.749,146.619 U40.1@170.749,147.053 170.749,148.848 C371.2@170.499,149.098 C369.2@170.499,151.257 ; v1(197.358,122.871) C351.2@198.374,122.871 C353.2@200.406,122.871 C353.2@200.471,122.871 ; U31.3@202.608,122.494 200.848,122.494 C353.2@200.471,122.871 ; U31.1@202.608,124.394 201.994,124.394 C353.2@200.471,122.871
  Top Layer w0.5: D2.2@123.53,124.333 123.53,125.562 124.317,126.349 C1.1@124.317,126.619 124.698,127 126.365,127 127.697,128.332 C2.1@127.697,129.286 C3.1@127.697,131.318 127.697,132.566 D7.1@128.651,133.52 ; C369.2@170.499,151.257 173.342,151.257 D3.1@174.117,150.482 174.139,150.504 R18.1@178.435,150.504 178.435,148.844 183.134,144.145 189.256,144.145 K1.5@190.354,145.243
  Bottom Layer w0.312: v1(128.143,134.747) 124.829,131.433 v1(124.829,121.92) 126.365,121.92 129.573,118.712 v1(130.657,118.712)
  Bottom Layer w0.5: v1(129.159,135.255) 129.159,135.509 138.601,144.951 v1(138.811,144.951) 140.97,147.11 140.97,152.4 ; v1(140.97,160.339) 140.97,152.4 ; v1(171.958,151.892) 171.958,152.4 140.97,152.4 ; H14.1@177.927,116.459 179.705,114.681 195.199,114.681 196.088,115.57 196.088,120.904 197.358,122.174 ; K1.5@190.354,145.243 190.354,138.957 197.358,131.953 v1(197.358,123.571)
  other v1: 128.651,134.747 129.159,134.747 128.143,135.255 128.651,135.255 172.72,151.892 171.958,152.527 172.72,152.527
AUX_CAN_CS: H11.3 H14.18 U41.11 | length 52.6
  Top Layer w0.2: H11.3@147.32,119.38 148.717,117.983 153.162,117.983 153.797,117.348 153.797,115.824 154.432,115.189 156.083,115.189 157.353,113.919 H14.18@157.607,113.919
  Top Layer w0.312: U41.11@147.172,142.111 151.64,142.111 154.432,139.319 v1(159.385,139.319) ; H11.3@147.32,119.38 149.479,121.539 151.003,121.539 v1(155.702,126.238)
  Bottom Layer w0.312: v1(155.702,126.238) 155.702,135.636 v1(159.385,139.319)
AUX_CAN_INT: H11.7 H14.20 U41.6 | length 56.5
  Top Layer w0.312: H11.7@137.16,119.38 137.16,122.936 142.494,128.27 142.494,145.288 145.667,148.461 U41.6@147.172,148.461
  Bottom Layer w0.2: H11.7@137.16,119.253 138.43,117.983 140.335,117.983 141.224,117.094 141.224,115.951 141.986,115.189 146.558,115.189 147.066,114.681 147.066,113.665 148.063,112.668 153.816,112.668 H14.20@155.067,113.919
CAN_H: CN1.3 CN1.5 U34.7 U36.1 | length 51
  Top Layer w0.2: CN1.5@116.672,132.018 CN1.5@111.672,132.018 110.109,133.581 110.109,137.455 CN1.3@111.672,139.018 CN1.3@116.672,139.018 ; v1(132.61,141.732) 132.864,141.478 U34.7@134.134,141.478 135.15,141.478 135.615,141.013 135.615,138.902 134.986,138.274 134.986,136.88 136.517,135.35 U36.1@136.906,135.35
  Bottom Layer w0.2: CN1.5@116.672,132.018 118.258,133.604 119.38,133.604 122.428,136.652 122.428,140.658 123.683,141.913 132.429,141.913 v1(132.61,141.732)
CAN_L: CN1.4 CN1.6 R16.2 U34.6 | length 51
  Top Layer w0.2: CN1.6@111.672,128.518 CN1.6@116.672,128.518 118.237,130.083 118.237,133.604 116.672,135.169 CN1.4@116.672,135.518 CN1.4@111.672,135.518 ; v1(130.555,138.041) 131.19,137.406 R16.2@131.191,135.754 ; v1(132.61,142.494) 132.864,142.748 U34.6@134.134,142.748
  Bottom Layer w0.2: CN1.4@116.672,135.518 116.672,135.235 117.795,134.112 119.253,134.112 121.92,136.779 121.92,140.716 123.517,142.313 132.429,142.313 v1(132.61,142.494) 132.842,142.494 133.35,141.986 133.35,140.837 v1(130.555,138.041)
CAN_RX: H14.24 U34.4 U41.29 | length 61.9
  Top Layer w0.2: U34.4@139.678,144.018 140.716,144.018 141.329,143.405 v1(141.329,142.494) ; v1(161.235,141.857) 162.349,141.857 162.717,142.225 162.934,142.225 163.453,142.744 163.453,142.961 163.873,143.381 U41.29@165.172,143.381
  Bottom Layer w0.2: H14.24@149.987,113.919 149.733,113.665 148.157,113.665 147.574,114.248 147.574,117.221 146.05,118.745 146.05,125.857 140.716,131.191 140.716,142.113 141.097,142.494 v1(141.329,142.494) 141.612,142.494 141.793,142.313 160.259,142.313 160.713,141.859 161.233,141.859 v1(161.235,141.857)
CAN_TX: H14.23 U34.1 U41.26 | length 61.9
  Top Layer w0.2: U34.1@139.678,140.208 140.589,140.208 141.351,140.97 141.351,141.71 v1(141.329,141.732) ; v1(161.235,141.222) 162.886,139.571 U41.26@165.172,139.571
  Bottom Layer w0.2: H14.23@149.987,116.459 149.279,116.459 148.59,117.148 148.59,120.523 148.17,120.943 146.994,120.943 146.685,121.252 146.685,121.793 146.939,122.047 148.082,122.047 148.449,122.414 148.449,122.873 148.056,123.265 146.945,123.265 146.685,123.525 146.685,123.95 146.885,124.15 147.645,124.15 147.955,124.46 147.955,124.86 141.329,131.486 v1(141.329,141.732) 141.51,141.913 159.966,141.913 160.657,141.222 v1(161.235,141.222)
DN: D1.3 H16.3 USB1.5 USB1.7 | length 18.9
  Top Layer w0.2: D1.3@122.44,121.42 122.432,121.412 v1(121.793,121.412) 121.781,121.4 121.781,120.684 122.059,120.406 USB1.5@122.059,119.596 122.059,118.923 122.308,118.674 122.836,118.674 123.059,118.897 USB1.7@123.059,119.596
  Bottom Layer w0.2: H16.3@113.284,123.444 113.284,122.648 113.758,122.174 114.091,122.174 114.452,122.535 114.806,122.535 115.168,122.174 116.586,122.174 117.075,122.663 117.075,124.014 117.375,124.314 117.658,124.314 117.831,124.141 118.041,124.141 118.214,124.314 118.51,124.314 118.913,123.911 118.913,123.417 119.224,123.106 119.718,123.106 119.964,122.86 119.964,121.794 120.346,121.412 v1(121.793,121.412)
DP: D1.1 H16.2 USB1.6 USB1.8 | length 18.9
  Top Layer w0.2: D1.1@122.44,122.42 v1(123.063,122.42) 123.063,120.525 123.061,120.523 ; USB1.6@122.559,119.596 122.559,120.273 122.809,120.523 123.061,120.523 ; USB1.8@123.559,119.596 123.571,119.608 123.571,120.269 123.317,120.523 123.061,120.523
  Bottom Layer w0.2: H16.2@110.744,123.444 112.014,124.714 118.676,124.714 120.97,122.42 v1(123.063,122.42)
